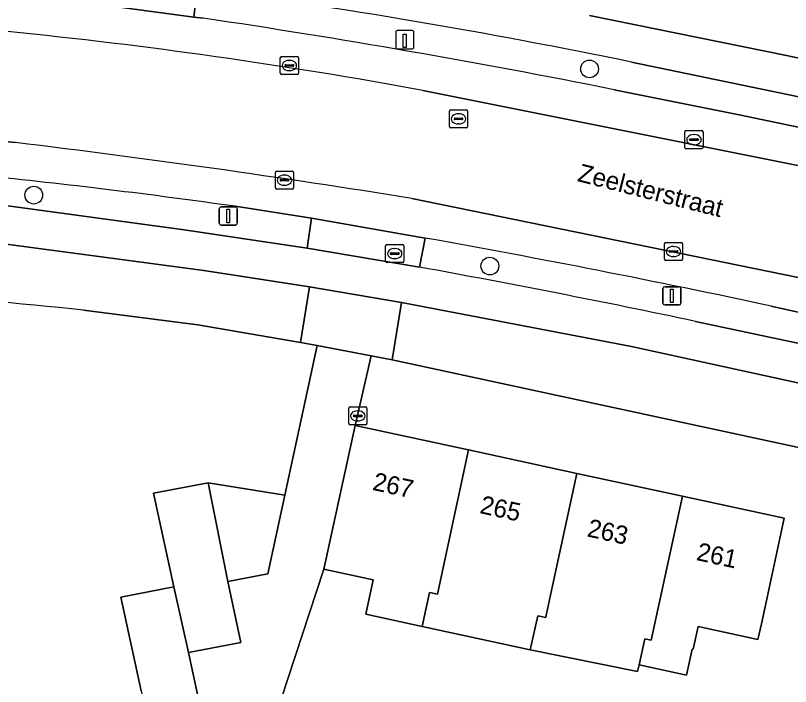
# Model space of a CAD drawing. Extents: x 158086 to 159499, y 382904 to 383981.
# Drawn here: x 158153.07 to 158195.83, y 383185.85 to 383222.86 of the extents above; entities that cross this region are included whole.
import ezdxf

# ---------------------------------------------------------------- set-up
doc = ezdxf.new("R2010")
doc.units = 0
for name, color, linetype in [('IMGEO_Berm_open', 7, 'Continuous'), ('IMGEO_Boom', 7, 'Continuous'), ('IMGEO_Erf', 7, 'Continuous'), ('IMGEO_Fietspad_gesloten', 7, 'Continuous'), ('IMGEO_Kolk', 7, 'Continuous'), ('IMGEO_Laadpaal', 7, 'Continuous'), ('IMGEO_Lichtmast', 7, 'Continuous'), ('IMGEO_Muur', 7, 'Continuous'), ('IMGEO_Openbare_ruimte_label', 7, 'Continuous'), ('IMGEO_Pand', 7, 'Continuous'), ('IMGEO_Pand_nummerreeks', 7, 'Continuous'), ('IMGEO_Parkeervlak_open', 7, 'Continuous'), ('IMGEO_Rijbaan_lokaal_gesloten', 7, 'Continuous'), ('IMGEO_Rijbaan_lokaal_open', 7, 'Continuous'), ('IMGEO_Rioolput', 7, 'Continuous'), ('IMGEO_Voetpad_open', 7, 'Continuous')]:
    doc.layers.add(name, color=color, linetype=linetype)

msp = doc.modelspace()

# ---------------------------------------------------------------- linework, layer by layer
at = {"layer": 'IMGEO_Berm_open'}
for points in [[(158163.083, 383224.375), (158162.898, 383222.77), (158163.418, 383222.713)], [(158276.869, 383198.965), (158310.165, 383191.768), (158320.914, 383189.662), (158321.216, 383191.287), (158309.726, 383193.572), (158241.35, 383208.396), (158202.859, 383217.005), (158187.053, 383220.294)], [(158186.095, 383218.765), (158192.996, 383217.388), (158201.806, 383215.545), (158240.906, 383206.806), (158256.997, 383203.295)], [(158142.625, 383213.717), (158162.381, 383211.046), (158169.16, 383210.021), (158169.396, 383211.678), (158165.179, 383212.334)], [(158175.665, 383210.584), (158175.353, 383208.981)], [(158190.588, 383205.987), (158197.351, 383204.538), (158197.724, 383206.166), (158194.754, 383206.832)]]:
    msp.add_lwpolyline(points, dxfattribs=at)
for centre, radius, start, end in [((158113.795, 382862.444), 365.272, 78.43044, 82.24513), ((158096.473, 382771.084), 456.564, 78.67949, 81.56842), ((158115.836, 382863.458), 352.349, 81.94983, 84.23336), ((158077.399, 382660.202), 559.085, 77.8832, 79.87699), ((158077.347, 382670.019), 547.8, 78.06985, 79.69385)]:
    msp.add_arc(centre, radius, start, end, dxfattribs=at)
at = {"layer": 'IMGEO_Boom'}
for centre in [(158184.739, 383219.912), (158154.075, 383212.95), (158179.238, 383209.036)]:
    msp.add_circle(centre, 0.489, dxfattribs=at)
at = {"layer": 'IMGEO_Erf'}
for points in [[(158160.008, 383185.608), (158158.875, 383190.779), (158161.807, 383191.346), (158160.678, 383196.502), (158163.696, 383197.073), (158167.932, 383196.408), (158169.712, 383204.665), (158168.797, 383204.821), (158163.12, 383205.788), (158156.824, 383206.605)], [(158199.44, 383198.357), (158173.847, 383203.865), (158172.697, 383204.087), (158171.8, 383200.251), (158178.062, 383198.895), (158184.041, 383197.6), (158189.864, 383196.339), (158195.479, 383195.123), (158194.421, 383190.237), (158194.219, 383189.304), (158194.033, 383188.443), (158190.733, 383189.157), (158190.461, 383187.9), (158190.397, 383187.914), (158190.082, 383186.467), (158187.473, 383187.034), (158187.394, 383186.667), (158181.465, 383187.873), (158175.506, 383189.165), (158172.392, 383189.84), (158172.802, 383191.732), (158170.082, 383192.321), (158167.733, 383185.145)]]:
    msp.add_lwpolyline(points, dxfattribs=at)
msp.add_arc((158139.519, 383051.584), 155.983, 83.63033, 87.6256, dxfattribs=at)
at = {"layer": 'IMGEO_Fietspad_gesloten'}
for points in [[(158310.224, 383195.595), (158241.603, 383210.483), (158207.946, 383218.002), (158195.608, 383220.653), (158184.729, 383222.86)], [(158187.053, 383220.294), (158202.859, 383217.005), (158241.35, 383208.396), (158309.726, 383193.572), (158321.216, 383191.287), (158327.206, 383190.282)], [(158175.353, 383208.981), (158169.16, 383210.021), (158162.381, 383211.046), (158142.625, 383213.717), (158139.242, 383214.246)], [(158138.36, 383212.086), (158139.992, 383211.926), (158163.458, 383208.795), (158169.284, 383207.897), (158174.364, 383207.03), (158187.059, 383204.599), (158306.699, 383178.457)], [(158307.14, 383180.487), (158201.292, 383203.669), (158197.351, 383204.538), (158190.588, 383205.987)]]:
    msp.add_lwpolyline(points, dxfattribs=at)
for centre, radius, start, end in [((158113.795, 382862.444), 365.272, 78.43044, 82.24513), ((158077.347, 382670.019), 547.8, 78.06985, 79.69385)]:
    msp.add_arc(centre, radius, start, end, dxfattribs=at)
at = {"layer": 'IMGEO_Kolk'}
for p, q in [((158167.752, 383220.601), (158168.604, 383220.601)), ((158167.677, 383219.675), (158167.677, 383220.527)), ((158168.165, 383220.381), (158168.19, 383220.381)), ((158168.678, 383220.527), (158168.678, 383219.675)), ((158167.936, 383220.095), (158167.936, 383220.107)), ((158168.374, 383220.058), (158167.976, 383220.058)), ((158167.979, 383220.144), (158168.377, 383220.144)), ((158168.188, 383219.821), (158168.163, 383219.821)), ((158168.42, 383220.107), (158168.42, 383220.095)), ((158168.604, 383219.601), (158167.752, 383219.601)), ((158190.001, 383215.585), (158190.001, 383216.437)), ((158190.076, 383216.511), (158190.928, 383216.511)), ((158191.002, 383216.437), (158191.002, 383215.585)), ((158190.26, 383216.005), (158190.26, 383216.017)), ((158190.698, 383215.968), (158190.3, 383215.968)), ((158190.303, 383216.054), (158190.701, 383216.054)), ((158190.489, 383216.291), (158190.514, 383216.291)), ((158190.744, 383216.017), (158190.744, 383216.005)), ((158190.928, 383215.511), (158190.076, 383215.511)), ((158190.512, 383215.731), (158190.487, 383215.731)), ((158167.403, 383213.35), (158167.403, 383214.202)), ((158167.478, 383214.276), (158168.33, 383214.276)), ((158168.404, 383214.202), (158168.404, 383213.35)), ((158167.662, 383213.77), (158167.662, 383213.782)), ((158167.705, 383213.819), (158168.103, 383213.819)), ((158167.891, 383214.056), (158167.916, 383214.056)), ((158168.146, 383213.782), (158168.146, 383213.77)), ((158168.1, 383213.733), (158167.702, 383213.733)), ((158167.914, 383213.496), (158167.889, 383213.496)), ((158168.33, 383213.276), (158167.478, 383213.276)), ((158188.949, 383210.339), (158189.801, 383210.339)), ((158188.874, 383209.413), (158188.874, 383210.265)), ((158189.362, 383210.119), (158189.387, 383210.119)), ((158189.875, 383210.265), (158189.875, 383209.413)), ((158189.133, 383209.833), (158189.133, 383209.845)), ((158189.571, 383209.796), (158189.173, 383209.796)), ((158189.176, 383209.882), (158189.574, 383209.882)), ((158189.385, 383209.559), (158189.36, 383209.559)), ((158189.617, 383209.845), (158189.617, 383209.833)), ((158189.801, 383209.339), (158188.949, 383209.339)), ((158171.449, 383200.347), (158171.449, 383201.199)), ((158171.524, 383201.273), (158172.376, 383201.273)), ((158171.937, 383201.053), (158171.962, 383201.053)), ((158172.45, 383201.199), (158172.45, 383200.347)), ((158171.708, 383200.767), (158171.708, 383200.779)), ((158172.146, 383200.73), (158171.748, 383200.73)), ((158171.751, 383200.816), (158172.149, 383200.816)), ((158171.96, 383200.493), (158171.935, 383200.493)), ((158172.192, 383200.779), (158172.192, 383200.767)), ((158172.376, 383200.273), (158171.524, 383200.273))]:
    msp.add_line(p, q, dxfattribs=at)
for points in [[(158167.752, 383220.601), (158168.604, 383220.601)], [(158167.677, 383219.675), (158167.677, 383220.527)], [(158168.678, 383220.527), (158168.678, 383219.675)], [(158168.604, 383219.601), (158167.752, 383219.601)], [(158190.001, 383215.585), (158190.001, 383216.437)], [(158190.076, 383216.511), (158190.928, 383216.511)], [(158191.002, 383216.437), (158191.002, 383215.585)], [(158190.928, 383215.511), (158190.076, 383215.511)], [(158167.403, 383213.35), (158167.403, 383214.202)], [(158167.478, 383214.276), (158168.33, 383214.276)], [(158168.404, 383214.202), (158168.404, 383213.35)], [(158168.33, 383213.276), (158167.478, 383213.276)], [(158188.949, 383210.339), (158189.801, 383210.339)], [(158188.874, 383209.413), (158188.874, 383210.265)], [(158189.875, 383210.265), (158189.875, 383209.413)], [(158189.801, 383209.339), (158188.949, 383209.339)], [(158171.449, 383200.347), (158171.449, 383201.199)], [(158171.524, 383201.273), (158172.376, 383201.273)], [(158172.45, 383201.199), (158172.45, 383200.347)], [(158172.376, 383200.273), (158171.524, 383200.273)]]:
    msp.add_lwpolyline(points, dxfattribs=at)
for centre, radius, start, end in [((158167.754, 383220.525), 0.0765, 91.552, 178.448), ((158167.754, 383220.525), 0.0765, 91.552, 178.448), ((158168.602, 383220.525), 0.0765, 1.552, 88.448), ((158168.602, 383220.525), 0.0765, 1.552, 88.448), ((158167.976, 383220.104), 0.0403, 85.8775, 175.7526), ((158167.973, 383220.094), 0.0366, 178.938, 274.7102), ((158168.377, 383220.101), 0.043, 264.8664, 352.4533), ((158168.381, 383220.106), 0.0386, 1.7309, 96.639), ((158167.754, 383219.677), 0.0765, 181.552, 268.448), ((158167.754, 383219.677), 0.0765, 181.552, 268.448), ((158168.602, 383219.677), 0.0765, 271.552, 358.448), ((158168.602, 383219.677), 0.0765, 271.552, 358.448), ((158190.078, 383216.435), 0.0765, 91.552, 178.448), ((158190.078, 383216.435), 0.0765, 91.552, 178.448), ((158190.926, 383216.435), 0.0765, 1.552, 88.448), ((158190.926, 383216.435), 0.0765, 1.552, 88.448), ((158190.3, 383216.014), 0.0403, 85.8775, 175.7526), ((158190.297, 383216.004), 0.0366, 178.938, 274.7102), ((158190.701, 383216.011), 0.043, 264.8664, 352.4533), ((158190.705, 383216.016), 0.0386, 1.7309, 96.639), ((158190.078, 383215.587), 0.0765, 181.552, 268.448), ((158190.078, 383215.587), 0.0765, 181.552, 268.448), ((158190.926, 383215.587), 0.0765, 271.552, 358.448), ((158190.926, 383215.587), 0.0765, 271.552, 358.448), ((158167.48, 383214.2), 0.0765, 91.552, 178.448), ((158167.48, 383214.2), 0.0765, 91.552, 178.448), ((158168.328, 383214.2), 0.0765, 1.552, 88.448), ((158168.328, 383214.2), 0.0765, 1.552, 88.448), ((158167.702, 383213.779), 0.0403, 85.8775, 175.7526), ((158167.699, 383213.769), 0.0366, 178.938, 274.7102), ((158168.103, 383213.776), 0.043, 264.8664, 352.4533), ((158168.107, 383213.781), 0.0386, 1.7309, 96.639), ((158167.48, 383213.352), 0.0765, 181.552, 268.448), ((158167.48, 383213.352), 0.0765, 181.552, 268.448), ((158168.328, 383213.352), 0.0765, 271.552, 358.448), ((158168.328, 383213.352), 0.0765, 271.552, 358.448), ((158188.951, 383210.263), 0.0765, 91.552, 178.448), ((158188.951, 383210.263), 0.0765, 91.552, 178.448), ((158189.799, 383210.263), 0.0765, 1.552, 88.448), ((158189.799, 383210.263), 0.0765, 1.552, 88.448), ((158189.173, 383209.842), 0.0403, 85.8775, 175.7526), ((158189.17, 383209.832), 0.0366, 178.938, 274.7102), ((158189.574, 383209.839), 0.043, 264.8664, 352.4533), ((158189.578, 383209.844), 0.0386, 1.7309, 96.639), ((158188.951, 383209.415), 0.0765, 181.552, 268.448), ((158188.951, 383209.415), 0.0765, 181.552, 268.448), ((158189.799, 383209.415), 0.0765, 271.552, 358.448), ((158189.799, 383209.415), 0.0765, 271.552, 358.448), ((158171.526, 383201.197), 0.0765, 91.552, 178.448), ((158171.526, 383201.197), 0.0765, 91.552, 178.448), ((158172.374, 383201.197), 0.0765, 1.552, 88.448), ((158172.374, 383201.197), 0.0765, 1.552, 88.448), ((158171.748, 383200.776), 0.0403, 85.8775, 175.7526), ((158171.745, 383200.766), 0.0366, 178.938, 274.7102), ((158172.149, 383200.773), 0.043, 264.8664, 352.4533), ((158172.153, 383200.778), 0.0386, 1.7309, 96.639), ((158171.526, 383200.349), 0.0765, 181.552, 268.448), ((158171.526, 383200.349), 0.0765, 181.552, 268.448), ((158172.374, 383200.349), 0.0765, 271.552, 358.448), ((158172.374, 383200.349), 0.0765, 271.552, 358.448)]:
    msp.add_arc(centre, radius, start, end, dxfattribs=at)
for centre, major_axis, ratio, start_param, end_param in [((158168.164, 383220.101), (-0.387, 0.002), 0.722429, 4.712389, 7.853982), ((158168.189, 383220.101), (-0.39, 0.002), 0.717154, 1.570796, 4.712389), ((158190.488, 383216.011), (-0.387, 0.002), 0.722429, 4.712389, 7.853982), ((158190.513, 383216.011), (-0.39, 0.002), 0.717154, 1.570796, 4.712389), ((158167.89, 383213.776), (-0.387, 0.002), 0.722429, 4.712389, 7.853982), ((158167.915, 383213.776), (-0.39, 0.002), 0.717154, 1.570796, 4.712389), ((158189.361, 383209.839), (-0.387, 0.002), 0.722429, 4.712389, 7.853982), ((158189.386, 383209.839), (-0.39, 0.002), 0.717154, 1.570796, 4.712389), ((158171.936, 383200.773), (-0.387, 0.002), 0.722429, 4.712389, 7.853982), ((158171.961, 383200.773), (-0.39, 0.002), 0.717154, 1.570796, 4.712389)]:
    msp.add_ellipse(centre, major_axis=major_axis, ratio=ratio, start_param=start_param, end_param=end_param, dxfattribs=at)
at = {"layer": 'IMGEO_Laadpaal'}
for p, q in [((158174.05, 383221.94), (158174.05, 383221.099)), ((158174.05, 383221.94), (158174.05, 383221.099)), ((158174.966, 383222.024), (158174.125, 383222.024)), ((158174.966, 383222.024), (158174.125, 383222.024)), ((158175.05, 383221.108), (158175.05, 383221.949)), ((158175.05, 383221.108), (158175.05, 383221.949)), ((158174.134, 383221.024), (158174.975, 383221.024)), ((158174.134, 383221.024), (158174.975, 383221.024))]:
    msp.add_line(p, q, dxfattribs=at)
msp.add_lwpolyline([(158174.465, 383221.837), (158174.625, 383221.837), (158174.625, 383221.104), (158174.465, 383221.104), (158174.465, 383221.837)], dxfattribs=at)
for centre, start, end in [((158174.128, 383221.946), 92.4484, 184.2845), ((158174.128, 383221.946), 92.4484, 184.2845), ((158174.972, 383221.946), 2.4484, 94.2845), ((158174.972, 383221.946), 2.4484, 94.2845), ((158174.128, 383221.102), 182.4484, 274.2845), ((158174.128, 383221.102), 182.4484, 274.2845), ((158174.972, 383221.102), 272.4484, 4.2845), ((158174.972, 383221.102), 272.4484, 4.2845)]:
    msp.add_arc(centre, 0.0779, start, end, dxfattribs=at)
at = {"layer": 'IMGEO_Lichtmast'}
for p, q in [((158164.311, 383211.401), (158164.311, 383212.201)), ((158164.311, 383212.201), (158164.311, 383211.401)), ((158164.411, 383212.301), (158165.201, 383212.301)), ((158165.201, 383212.301), (158164.411, 383212.301)), ((158165.301, 383212.201), (158165.301, 383211.401)), ((158165.301, 383211.401), (158165.301, 383212.201)), ((158165.201, 383211.301), (158164.411, 383211.301)), ((158164.411, 383211.301), (158165.201, 383211.301)), ((158188.791, 383206.997), (158188.791, 383207.797)), ((158188.791, 383207.797), (158188.791, 383206.997)), ((158188.891, 383207.897), (158189.681, 383207.897)), ((158189.681, 383207.897), (158188.891, 383207.897)), ((158189.781, 383207.797), (158189.781, 383206.997)), ((158189.781, 383206.997), (158189.781, 383207.797)), ((158189.681, 383206.897), (158188.891, 383206.897)), ((158188.891, 383206.897), (158189.681, 383206.897))]:
    msp.add_line(p, q, dxfattribs=at)
for points in [[(158164.731, 383212.176), (158164.881, 383212.176), (158164.881, 383211.426), (158164.731, 383211.426), (158164.731, 383212.176)], [(158189.211, 383207.772), (158189.361, 383207.772), (158189.361, 383207.022), (158189.211, 383207.022), (158189.211, 383207.772)]]:
    msp.add_lwpolyline(points, dxfattribs=at)
for centre, start, end in [((158164.411, 383212.201), 90, 180), ((158164.411, 383212.201), 90, 180), ((158165.201, 383212.201), 0, 90), ((158165.201, 383212.201), 360, 90), ((158164.411, 383211.401), 180, 270), ((158164.411, 383211.401), 180, 270), ((158165.201, 383211.401), 270, 0), ((158165.201, 383211.401), 270, 0), ((158188.891, 383207.797), 90, 180), ((158188.891, 383207.797), 90, 180), ((158189.681, 383207.797), 0, 90), ((158189.681, 383207.797), 360, 90), ((158188.891, 383206.997), 180, 270), ((158188.891, 383206.997), 180, 270), ((158189.681, 383206.997), 270, 0), ((158189.681, 383206.997), 270, 0)]:
    msp.add_arc(centre, 0.1, start, end, dxfattribs=at)
at = {"layer": 'IMGEO_Muur'}
for points in [[(158163.12, 383205.788), (158156.824, 383206.605)], [(158168.797, 383204.821), (158163.12, 383205.788)], [(158169.712, 383204.665), (158168.797, 383204.821)]]:
    msp.add_lwpolyline(points, dxfattribs=at)
msp.add_arc((158139.519, 383051.584), 155.983, 83.63033, 87.6256, dxfattribs=at)
at = {"layer": 'IMGEO_Pand'}
for points in [[(158176.342, 383190.944), (158178.062, 383198.895), (158171.8, 383200.251), (158170.082, 383192.321), (158172.802, 383191.732), (158172.392, 383189.84), (158175.506, 383189.165), (158175.913, 383191.037)], [(158184.041, 383197.6), (158178.062, 383198.895), (158176.342, 383190.944), (158175.913, 383191.037), (158175.506, 383189.165), (158181.465, 383187.873), (158181.888, 383189.753), (158182.322, 383189.659), (158182.366, 383189.861), (158182.7, 383191.403)], [(158189.864, 383196.339), (158184.041, 383197.6), (158182.7, 383191.403), (158182.366, 383189.861), (158182.322, 383189.659), (158181.888, 383189.753), (158181.465, 383187.873), (158187.394, 383186.667), (158187.473, 383187.034), (158187.788, 383188.48), (158188.146, 383188.402)], [(158162.607, 383187.713), (158165.501, 383188.273), (158164.784, 383191.645), (158163.696, 383197.073), (158160.678, 383196.502), (158161.807, 383191.346)], [(158167.932, 383196.408), (158163.696, 383197.073), (158164.784, 383191.645), (158166.995, 383192.065)], [(158189.864, 383196.339), (158188.146, 383188.402), (158187.788, 383188.48), (158187.473, 383187.034), (158190.082, 383186.467), (158190.397, 383187.914), (158190.461, 383187.9), (158190.733, 383189.157), (158194.033, 383188.443), (158194.219, 383189.304), (158194.421, 383190.237), (158195.479, 383195.123)], [(158161.807, 383191.346), (158158.875, 383190.779), (158160.008, 383185.608), (158160.827, 383181.868), (158163.759, 383182.435), (158162.607, 383187.713)]]:
    msp.add_lwpolyline(points, close=True, dxfattribs=at)
at = {"layer": 'IMGEO_Parkeervlak_open'}
for points in [[(158163.418, 383222.713), (158162.898, 383222.77), (158158.929, 383223.306), (158153.476, 383223.894), (158148.453, 383224.408)], [(158175.54, 383218.731), (158201.478, 383213.544), (158241.385, 383204.641), (158259.571, 383200.688)], [(158256.997, 383203.295), (158240.906, 383206.806), (158201.806, 383215.545), (158192.996, 383217.388), (158186.095, 383218.765)], [(158153.066, 383215.846), (158150.268, 383216.113), (158144.556, 383216.641)], [(158258.327, 383194.843), (158206.139, 383206.386), (158174.939, 383212.762)], [(158165.179, 383212.334), (158169.396, 383211.678), (158175.665, 383210.584)], [(158194.754, 383206.832), (158197.724, 383206.166), (158201.626, 383205.353), (158236.292, 383197.608), (158254.9, 383193.55)]]:
    msp.add_lwpolyline(points, dxfattribs=at)
for centre, radius, start, end in [((158096.473, 382771.084), 456.564, 78.67949, 81.56842), ((158123.913, 382936.802), 286.617, 79.62285, 84.25205), ((158089.26, 382684.197), 535.465, 80.79256, 83.15633), ((158115.836, 382863.458), 352.349, 81.94983, 84.23336), ((158077.399, 382660.202), 559.085, 77.8832, 79.87699)]:
    msp.add_arc(centre, radius, start, end, dxfattribs=at)
at = {"layer": 'IMGEO_Rijbaan_lokaal_gesloten'}
for points in [[(158174.939, 383212.762), (158206.139, 383206.386), (158258.327, 383194.843), (158258.527, 383194.795), (158259.738, 383200.649), (158259.571, 383200.688), (158241.385, 383204.641), (158201.478, 383213.544), (158175.54, 383218.731)], [(158139.954, 383217.066), (158143.441, 383216.748), (158144.556, 383216.641), (158150.268, 383216.113), (158153.066, 383215.846)]]:
    msp.add_lwpolyline(points, dxfattribs=at)
for centre, radius, start, end in [((158123.913, 382936.802), 286.617, 79.62285, 84.25205), ((158089.26, 382684.197), 535.465, 80.79256, 83.15633)]:
    msp.add_arc(centre, radius, start, end, dxfattribs=at)
at = {"layer": 'IMGEO_Rijbaan_lokaal_open'}
msp.add_lwpolyline([(158167.733, 383185.145), (158170.082, 383192.321), (158171.8, 383200.251), (158172.697, 383204.087), (158169.712, 383204.665), (158167.932, 383196.408), (158166.995, 383192.065), (158164.784, 383191.645), (158165.501, 383188.273), (158162.607, 383187.713), (158163.759, 383182.435)], dxfattribs=at)
at = {"layer": 'IMGEO_Rioolput'}
for p, q in [((158177.088, 383217.66), (158177.94, 383217.66)), ((158177.013, 383216.734), (158177.013, 383217.586)), ((158177.272, 383217.154), (158177.272, 383217.166)), ((158177.315, 383217.203), (158177.713, 383217.203)), ((158177.501, 383217.44), (158177.526, 383217.44)), ((158177.756, 383217.166), (158177.756, 383217.154)), ((158178.014, 383217.586), (158178.014, 383216.734)), ((158177.71, 383217.117), (158177.312, 383217.117)), ((158177.524, 383216.88), (158177.499, 383216.88)), ((158177.94, 383216.66), (158177.088, 383216.66)), ((158173.489, 383209.301), (158173.489, 383210.153)), ((158173.564, 383210.227), (158174.416, 383210.227)), ((158173.977, 383210.007), (158174.002, 383210.007)), ((158174.49, 383210.153), (158174.49, 383209.301)), ((158173.748, 383209.721), (158173.748, 383209.733)), ((158174.186, 383209.684), (158173.788, 383209.684)), ((158173.791, 383209.77), (158174.189, 383209.77)), ((158174.232, 383209.733), (158174.232, 383209.721)), ((158174.416, 383209.227), (158173.564, 383209.227)), ((158174, 383209.447), (158173.975, 383209.447))]:
    msp.add_line(p, q, dxfattribs=at)
for points in [[(158177.088, 383217.66), (158177.94, 383217.66)], [(158177.013, 383216.734), (158177.013, 383217.586)], [(158178.014, 383217.586), (158178.014, 383216.734)], [(158177.94, 383216.66), (158177.088, 383216.66)], [(158173.489, 383209.301), (158173.489, 383210.153)], [(158173.564, 383210.227), (158174.416, 383210.227)], [(158174.49, 383210.153), (158174.49, 383209.301)], [(158174.416, 383209.227), (158173.564, 383209.227)]]:
    msp.add_lwpolyline(points, dxfattribs=at)
for centre, radius, start, end in [((158177.09, 383217.584), 0.0765, 91.552, 178.448), ((158177.09, 383217.584), 0.0765, 91.552, 178.448), ((158177.938, 383217.584), 0.0765, 1.552, 88.448), ((158177.938, 383217.584), 0.0765, 1.552, 88.448), ((158177.312, 383217.163), 0.0403, 85.8775, 175.7526), ((158177.717, 383217.165), 0.0386, 1.7309, 96.639), ((158177.09, 383216.736), 0.0765, 181.552, 268.448), ((158177.09, 383216.736), 0.0765, 181.552, 268.448), ((158177.309, 383217.153), 0.0366, 178.938, 274.7102), ((158177.713, 383217.16), 0.043, 264.8664, 352.4533), ((158177.938, 383216.736), 0.0765, 271.552, 358.448), ((158177.938, 383216.736), 0.0765, 271.552, 358.448), ((158173.566, 383210.151), 0.0765, 91.552, 178.448), ((158173.566, 383210.151), 0.0765, 91.552, 178.448), ((158174.414, 383210.151), 0.0765, 1.552, 88.448), ((158174.414, 383210.151), 0.0765, 1.552, 88.448), ((158173.788, 383209.73), 0.0403, 85.8775, 175.7526), ((158173.785, 383209.72), 0.0366, 178.938, 274.7102), ((158174.189, 383209.727), 0.043, 264.8664, 352.4533), ((158174.193, 383209.732), 0.0386, 1.7309, 96.639), ((158173.566, 383209.303), 0.0765, 181.552, 268.448), ((158173.566, 383209.303), 0.0765, 181.552, 268.448), ((158174.414, 383209.303), 0.0765, 271.552, 358.448), ((158174.414, 383209.303), 0.0765, 271.552, 358.448)]:
    msp.add_arc(centre, radius, start, end, dxfattribs=at)
for centre, major_axis, ratio, start_param, end_param in [((158177.5, 383217.16), (-0.387, 0.002), 0.722429, 4.712389, 7.853982), ((158177.525, 383217.16), (-0.39, 0.002), 0.717154, 1.570796, 4.712389), ((158173.976, 383209.727), (-0.387, 0.002), 0.722429, 4.712389, 7.853982), ((158174.001, 383209.727), (-0.39, 0.002), 0.717154, 1.570796, 4.712389)]:
    msp.add_ellipse(centre, major_axis=major_axis, ratio=ratio, start_param=start_param, end_param=end_param, dxfattribs=at)
at = {"layer": 'IMGEO_Voetpad_open'}
for points in [[(158158.929, 383223.306), (158162.898, 383222.77), (158163.083, 383224.375), (158159.127, 383224.909)], [(158169.16, 383210.021), (158175.353, 383208.981), (158175.665, 383210.584), (158169.396, 383211.678)], [(158173.847, 383203.865), (158174.364, 383207.03), (158169.284, 383207.897), (158168.797, 383204.821), (158169.712, 383204.665), (158172.697, 383204.087)]]:
    msp.add_lwpolyline(points, close=True, dxfattribs=at)
for points in [[(158184.729, 383222.86), (158195.608, 383220.653), (158207.946, 383218.002), (158241.603, 383210.483), (158310.224, 383195.595)], [(158156.824, 383206.605), (158163.12, 383205.788), (158168.797, 383204.821), (158169.284, 383207.897), (158163.458, 383208.795), (158139.992, 383211.926)], [(158306.699, 383178.457), (158187.059, 383204.599), (158174.364, 383207.03), (158173.847, 383203.865), (158199.44, 383198.357), (158205.144, 383197.12), (158210.958, 383195.86), (158216.769, 383194.601), (158222.593, 383193.338)]]:
    msp.add_lwpolyline(points, dxfattribs=at)
msp.add_arc((158139.519, 383051.584), 155.983, 83.63033, 87.6256, dxfattribs=at)

# ---------------------------------------------------------------- texts
at = {"layer": 'IMGEO_Openbare_ruimte_label'}
msp.add_text('Zeelsterstraat', height=1, rotation=345.8108, dxfattribs=at).set_placement((158184.026, 383213.731))
at = {"layer": 'IMGEO_Pand_nummerreeks'}
for s, rotation, p in [('267', 347.7805, (158172.718, 383196.697)), ('265', 347.7788, (158178.638, 383195.415)), ('263', 347.7788, (158184.558, 383194.133)), ('261', 347.7788, (158190.587, 383192.827))]:
    msp.add_text(s, height=1, rotation=rotation, dxfattribs=at).set_placement(p)

doc.saveas('drawing.dxf')
